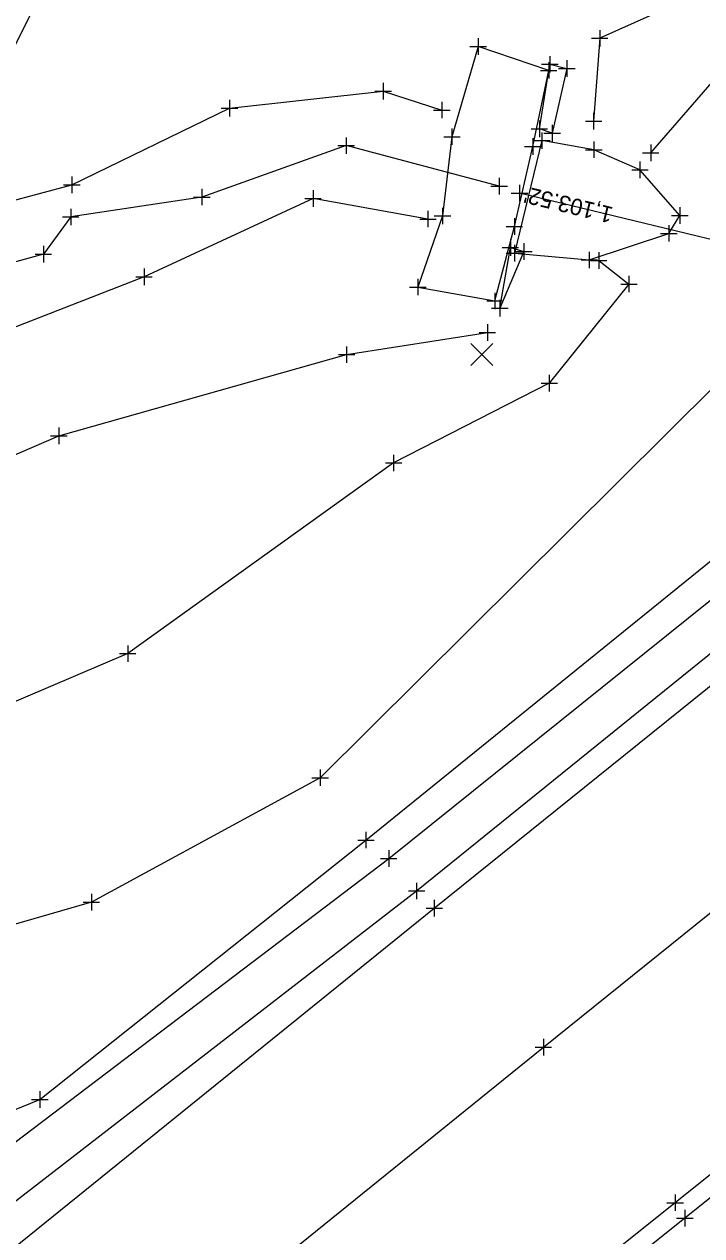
# Model space of a CAD drawing. Extents: x 2184635 to 2185378, y 369880 to 370486.
# Drawn here: x 2185068.3 to 2185109.3, y 370246.3 to 370319.8 of the extents above; entities that cross this region are included whole.
import ezdxf

# ---------------------------------------------------------------- set-up
doc = ezdxf.new("R2010")
doc.units = 0
for name, color, linetype in [('_CIVIL_CONSTRUCTION', 7, 'Continuous'), ('DR_X_Ditch', 7, 'Continuous'), ('DR_X_Headwall', 7, 'Continuous'), ('DR_X_Storm_Sewer', 7, 'Continuous'), ('GE_X_Alignment_100_Distances', 7, 'Continuous'), ('PM_X_CL_Pass_Proh_Lt', 7, 'Continuous'), ('PM_X_CL_Pass_Proh_Rt', 7, 'Continuous'), ('PM_X_Edge_Line', 7, 'Continuous'), ('PV_X_COP', 7, 'Continuous'), ('PV_X_EOP', 7, 'Continuous'), ('PV_X_Shoulder', 7, 'Continuous'), ('RD_X_Concrete_Pad', 7, 'Continuous'), ('RD_X_GR_Lt', 7, 'Continuous'), ('RW_X_CL', 7, 'Continuous'), ('RW_X_CL_100_Bearings', 7, 'Continuous'), ('SC_Scratch1', 7, 'Continuous'), ('SV_X_Break_Lines', 7, 'Continuous'), ('SV_X_Terrain_Boundary', 7, 'Continuous'), ('SV_X_Void_Area', 7, 'Continuous')]:
    doc.layers.add(name, color=color, linetype=linetype)

msp = doc.modelspace()

# ---------------------------------------------------------------- linework, layer by layer
at = {"layer": '_CIVIL_CONSTRUCTION'}
for p, q in [((2185095.352, 370299.089), (2185096.685, 370300.424)), ((2185095.352, 370300.424), (2185096.685, 370299.089))]:
    msp.add_line(p, q, dxfattribs=at)
at = {"layer": 'DR_X_Ditch'}
msp.add_lwpolyline([(2185097.066, 370309.962), (2185087.789, 370312.42), (2185079.038, 370309.308), (2185071.088, 370308.099), (2185069.431, 370305.844), (2185053.728, 370301.514), (2185050.899, 370302.622)], dxfattribs=at)
at = {"layer": 'DR_X_Headwall'}
for points in [[(2185100.132, 370317.35), (2185101.169, 370317.094), (2185100.276, 370313.173), (2185099.501, 370313.442)], [(2185097.746, 370306.249), (2185098.566, 370306.002), (2185097.102, 370302.573)]]:
    msp.add_lwpolyline(points, close=True, dxfattribs=at)
at = {"layer": 'DR_X_Storm_Sewer'}
msp.add_line((2185197.669, 370285.467), (2185098.296, 370309.544), dxfattribs=at)
at = {"layer": 'GE_X_Alignment_100_Distances'}
msp.add_lwpolyline([(2185064.938, 370249.915), (2185090.369, 370269.214), (2185130.506, 370301.429), (2185168.462, 370331.991), (2185206.748, 370363.667), (2185245.64, 370395.454)], dxfattribs=at)
at = {"layer": 'PM_X_CL_Pass_Proh_Lt'}
msp.add_lwpolyline([(2185262.142, 370374.202), (2185223.699, 370342.03), (2185185.178, 370310.659), (2185146.677, 370279.544), (2185107.738, 370248.35), (2185068.5, 370216.963), (2185029.051, 370186.04), (2184989.472, 370156.275), (2184949.89, 370125.369), (2184910.765, 370094.563), (2184870.979, 370063.529), (2184832.077, 370032.401), (2184793.204, 370001.486), (2184754.34, 369970.024), (2184715.121, 369938.505), (2184676.144, 369907.221)], dxfattribs=at)
at = {"layer": 'PM_X_CL_Pass_Proh_Rt'}
msp.add_lwpolyline([(2184772.075, 369998.33), (2184786.357, 370009.443), (2184824.962, 370040.257), (2184864.241, 370071.885), (2184905.968, 370104.805), (2184943.399, 370133.995), (2184983.483, 370165.213), (2185020.257, 370194.467), (2185061.224, 370226.635), (2185099.743, 370257.779), (2185139.182, 370289.511), (2185177.352, 370320.307), (2185216.054, 370351.804), (2185254.728, 370383.452)], dxfattribs=at)
at = {"layer": 'PM_X_Edge_Line'}
msp.add_lwpolyline([(2184661.525, 369922.948), (2184702.122, 369955.424), (2184740.459, 369986.306), (2184779.792, 370018.036), (2184818.421, 370048.832), (2184857.458, 370080.192), (2184899.139, 370112.801), (2184937.357, 370142.735), (2184976.78, 370173.64), (2185013.226, 370203.926), (2185054.743, 370235.213), (2185093.131, 370266.204), (2185132.902, 370298.208), (2185170.876, 370328.987), (2185209.713, 370360.437), (2185248.243, 370392.049)], dxfattribs=at)
at = {"layer": 'PV_X_COP'}
msp.add_lwpolyline([(2184667.936, 369914.544), (2184708.437, 369946.755), (2184746.444, 369977.522), (2184786.357, 370009.443), (2184824.962, 370040.257), (2184864.241, 370071.885), (2184905.968, 370104.805), (2184943.399, 370133.995), (2184983.483, 370165.213), (2185020.257, 370194.467), (2185061.224, 370226.635), (2185099.743, 370257.779), (2185139.182, 370289.511), (2185177.352, 370320.307), (2185216.054, 370351.804), (2185254.679, 370383.196)], dxfattribs=at)
at = {"layer": 'PV_X_EOP'}
for points in [[(2184661.562, 369922.858), (2184702.122, 369955.424), (2184740.459, 369986.306), (2184779.792, 370018.036), (2184818.421, 370048.832), (2184857.458, 370080.192), (2184899.139, 370112.801), (2184937.357, 370142.735), (2184976.78, 370173.64), (2185013.226, 370203.926), (2185054.743, 370235.213), (2185093.131, 370266.204), (2185132.902, 370298.208), (2185170.876, 370328.987), (2185209.713, 370360.437), (2185248.181, 370392.045)], [(2185262.152, 370374.256), (2185223.699, 370342.03), (2185185.178, 370310.659), (2185146.677, 370279.544), (2185107.738, 370248.35), (2185068.5, 370216.963), (2185029.051, 370186.04), (2184989.472, 370156.275), (2184949.89, 370125.369), (2184910.765, 370094.563), (2184870.979, 370063.529), (2184832.077, 370032.401), (2184793.204, 370001.486), (2184754.34, 369970.024), (2184715.121, 369938.505), (2184676.223, 369907.131)]]:
    msp.add_lwpolyline(points, dxfattribs=at)
at = {"layer": 'PV_X_Shoulder'}
for points in [[(2184660.616, 369924.653), (2184701.177, 369956.993), (2184739.308, 369987.689), (2184778.66, 370019.08), (2184817.145, 370050.202), (2184856.424, 370081.402), (2184897.962, 370114.276), (2184936.317, 370143.726), (2184975.811, 370174.815), (2184986.608, 370184.308), (2184994.082, 370192.548), (2185011.043, 370206.648), (2185033.171, 370224.287), (2185051.814, 370238.9), (2185062.885, 370246.964), (2185064.956, 370248.001), (2185067.328, 370248.113), (2185092.06, 370267.243), (2185132.002, 370299.513), (2185169.971, 370330.255), (2185208.837, 370361.607), (2185247.242, 370392.983)], [(2185263.127, 370373.08), (2185224.626, 370341.08), (2185185.979, 370309.587), (2185147.251, 370278.484), (2185108.316, 370247.412), (2185069.303, 370216.141), (2185029.865, 370185.151), (2184990.36, 370154.899), (2184951.083, 370123.826), (2184911.784, 370093.315), (2184872.077, 370062.156), (2184833.336, 370030.958), (2184794.18, 369999.967), (2184755.603, 369968.652), (2184716.02, 369937.324), (2184677.487, 369905.633)]]:
    msp.add_lwpolyline(points, dxfattribs=at)
at = {"layer": 'RD_X_Concrete_Pad'}
msp.add_lwpolyline([(2185094.202, 370312.964), (2185093.625, 370308.161), (2185092.134, 370303.852), (2185096.808, 370303.006), (2185097.986, 370307.52), (2185099.103, 370312.374), (2185100.067, 370316.984), (2185095.792, 370318.426)], close=True, dxfattribs=at)
at = {"layer": 'RD_X_GR_Lt'}
msp.add_lwpolyline([(2185046.02, 370255.484), (2185051.058, 370252.105), (2185059.685, 370250.72), (2185069.217, 370254.599), (2185088.99, 370270.332), (2185128.498, 370302.326), (2185166.722, 370333.304), (2185205.522, 370364.756), (2185244.075, 370396.55), (2185351.751, 370485.271)], dxfattribs=at)
at = {"layer": 'RW_X_CL'}
for p, q in [((2185095.792, 370318.926), (2185095.792, 370317.926)), ((2185102.66, 370318.931), (2185103.66, 370318.931)), ((2185103.16, 370319.431), (2185103.16, 370318.431)), ((2185103.16, 370318.931), (2185103.16, 370318.931)), ((2185095.292, 370318.426), (2185096.292, 370318.426)), ((2185095.792, 370318.426), (2185095.792, 370318.426)), ((2185099.632, 370317.35), (2185100.632, 370317.35)), ((2185100.067, 370317.484), (2185100.067, 370316.484)), ((2185100.132, 370317.85), (2185100.132, 370316.85)), ((2185100.132, 370317.35), (2185100.132, 370317.35)), ((2185101.169, 370317.594), (2185101.169, 370316.594)), ((2185099.567, 370316.984), (2185100.567, 370316.984)), ((2185100.067, 370316.984), (2185100.067, 370316.984)), ((2185100.669, 370317.094), (2185101.669, 370317.094)), ((2185101.169, 370317.094), (2185101.169, 370317.094)), ((2185090.033, 370316.221), (2185090.033, 370315.221)), ((2185080.719, 370315.196), (2185080.719, 370314.196)), ((2185089.533, 370315.721), (2185090.533, 370315.721)), ((2185090.033, 370315.721), (2185090.033, 370315.721)), ((2185080.219, 370314.696), (2185081.219, 370314.696)), ((2185080.719, 370314.696), (2185080.719, 370314.696)), ((2185093.093, 370314.581), (2185094.093, 370314.581)), ((2185093.593, 370315.081), (2185093.593, 370314.081)), ((2185093.593, 370314.581), (2185093.593, 370314.581)), ((2185102.793, 370314.409), (2185102.793, 370313.409)), ((2185099.501, 370313.942), (2185099.501, 370312.942)), ((2185100.276, 370313.673), (2185100.276, 370312.673)), ((2185102.293, 370313.909), (2185103.293, 370313.909)), ((2185102.793, 370313.909), (2185102.793, 370313.909)), ((2185087.789, 370312.92), (2185087.789, 370311.92)), ((2185093.702, 370312.964), (2185094.702, 370312.964)), ((2185094.202, 370313.464), (2185094.202, 370312.464)), ((2185094.202, 370312.964), (2185094.202, 370312.964)), ((2185099.001, 370313.442), (2185100.001, 370313.442)), ((2185099.501, 370313.442), (2185099.501, 370313.442)), ((2185099.651, 370313.228), (2185099.651, 370312.228)), ((2185099.776, 370313.173), (2185100.776, 370313.173)), ((2185100.276, 370313.173), (2185100.276, 370313.173)), ((2185087.289, 370312.42), (2185088.289, 370312.42)), ((2185087.789, 370312.42), (2185087.789, 370312.42)), ((2185098.603, 370312.374), (2185099.603, 370312.374)), ((2185099.103, 370312.874), (2185099.103, 370311.874)), ((2185099.103, 370312.374), (2185099.103, 370312.374)), ((2185099.151, 370312.728), (2185100.151, 370312.728)), ((2185099.651, 370312.728), (2185099.651, 370312.728)), ((2185102.802, 370312.677), (2185102.802, 370311.677)), ((2185106.25, 370312.484), (2185106.25, 370311.484)), ((2185102.302, 370312.177), (2185103.302, 370312.177)), ((2185102.802, 370312.177), (2185102.802, 370312.177)), ((2185105.597, 370311.451), (2185105.597, 370310.451)), ((2185105.75, 370311.984), (2185106.75, 370311.984)), ((2185106.25, 370311.984), (2185106.25, 370311.984)), ((2185105.097, 370310.951), (2185106.097, 370310.951)), ((2185105.597, 370310.951), (2185105.597, 370310.951)), ((2185070.662, 370310.043), (2185071.662, 370310.043)), ((2185071.162, 370310.543), (2185071.162, 370309.543)), ((2185071.162, 370310.043), (2185071.162, 370310.043)), ((2185097.066, 370310.462), (2185097.066, 370309.462)), ((2185078.538, 370309.308), (2185079.538, 370309.308)), ((2185079.038, 370309.808), (2185079.038, 370308.808)), ((2185079.038, 370309.308), (2185079.038, 370309.308)), ((2185085.782, 370309.719), (2185085.782, 370308.719)), ((2185096.566, 370309.962), (2185097.566, 370309.962)), ((2185097.066, 370309.962), (2185097.066, 370309.962)), ((2185071.088, 370308.599), (2185071.088, 370307.599)), ((2185085.282, 370309.219), (2185086.282, 370309.219)), ((2185085.782, 370309.219), (2185085.782, 370309.219)), ((2185093.625, 370308.661), (2185093.625, 370307.661)), ((2185108.016, 370308.685), (2185108.016, 370307.685)), ((2185070.588, 370308.099), (2185071.588, 370308.099)), ((2185071.088, 370308.099), (2185071.088, 370308.099)), ((2185092.248, 370307.972), (2185093.248, 370307.972)), ((2185092.748, 370308.472), (2185092.748, 370307.472)), ((2185092.748, 370307.972), (2185092.748, 370307.972)), ((2185093.125, 370308.161), (2185094.125, 370308.161)), ((2185093.625, 370308.161), (2185093.625, 370308.161)), ((2185097.986, 370308.02), (2185097.986, 370307.02)), ((2185107.516, 370308.185), (2185108.516, 370308.185)), ((2185108.016, 370308.185), (2185108.016, 370308.185)), ((2185097.486, 370307.52), (2185098.486, 370307.52)), ((2185097.986, 370307.52), (2185097.986, 370307.52)), ((2185106.846, 370307.101), (2185107.846, 370307.101)), ((2185107.346, 370307.601), (2185107.346, 370306.601)), ((2185107.346, 370307.101), (2185107.346, 370307.101)), ((2185069.431, 370306.344), (2185069.431, 370305.344)), ((2185097.746, 370306.749), (2185097.746, 370305.749)), ((2185097.992, 370306.404), (2185097.992, 370305.404)), ((2185098.566, 370306.502), (2185098.566, 370305.502)), ((2185068.931, 370305.844), (2185069.931, 370305.844)), ((2185069.431, 370305.844), (2185069.431, 370305.844)), ((2185097.246, 370306.249), (2185098.246, 370306.249)), ((2185097.492, 370305.904), (2185098.492, 370305.904)), ((2185097.746, 370306.249), (2185097.746, 370306.249)), ((2185097.992, 370305.904), (2185097.992, 370305.904)), ((2185098.066, 370306.002), (2185099.066, 370306.002)), ((2185098.566, 370306.002), (2185098.566, 370306.002)), ((2185102.527, 370305.99), (2185102.527, 370304.99)), ((2185103.101, 370305.956), (2185103.101, 370304.956)), ((2185075.536, 370304.974), (2185075.536, 370303.974)), ((2185102.027, 370305.49), (2185103.027, 370305.49)), ((2185102.527, 370305.49), (2185102.527, 370305.49)), ((2185102.601, 370305.456), (2185103.601, 370305.456)), ((2185103.101, 370305.456), (2185103.101, 370305.456)), ((2185075.036, 370304.474), (2185076.036, 370304.474)), ((2185075.536, 370304.474), (2185075.536, 370304.474)), ((2185092.134, 370304.352), (2185092.134, 370303.352)), ((2185104.93, 370304.533), (2185104.93, 370303.533)), ((2185091.634, 370303.852), (2185092.634, 370303.852)), ((2185092.134, 370303.852), (2185092.134, 370303.852)), ((2185096.808, 370303.506), (2185096.808, 370302.506)), ((2185104.43, 370304.033), (2185105.43, 370304.033)), ((2185104.93, 370304.033), (2185104.93, 370304.033)), ((2185096.308, 370303.006), (2185097.308, 370303.006)), ((2185096.808, 370303.006), (2185096.808, 370303.006)), ((2185097.102, 370303.073), (2185097.102, 370302.073)), ((2185096.602, 370302.573), (2185097.602, 370302.573)), ((2185097.102, 370302.573), (2185097.102, 370302.573)), ((2185096.348, 370301.593), (2185096.348, 370300.593)), ((2185095.848, 370301.093), (2185096.848, 370301.093)), ((2185096.348, 370301.093), (2185096.348, 370301.093)), ((2185087.315, 370299.755), (2185088.315, 370299.755)), ((2185087.815, 370300.255), (2185087.815, 370299.255)), ((2185087.815, 370299.755), (2185087.815, 370299.755)), ((2185100.103, 370298.521), (2185100.103, 370297.521)), ((2185099.603, 370298.021), (2185100.603, 370298.021)), ((2185100.103, 370298.021), (2185100.103, 370298.021)), ((2185070.374, 370295.331), (2185070.374, 370294.331)), ((2185069.874, 370294.831), (2185070.874, 370294.831)), ((2185070.374, 370294.831), (2185070.374, 370294.831)), ((2185090.168, 370293.19), (2185091.168, 370293.19)), ((2185090.668, 370293.69), (2185090.668, 370292.69)), ((2185090.668, 370293.19), (2185090.668, 370293.19)), ((2185074.547, 370282.128), (2185074.547, 370281.128)), ((2185074.047, 370281.628), (2185075.047, 370281.628)), ((2185074.547, 370281.628), (2185074.547, 370281.628)), ((2185085.714, 370274.11), (2185086.714, 370274.11)), ((2185086.214, 370274.61), (2185086.214, 370273.61)), ((2185086.214, 370274.11), (2185086.214, 370274.11)), ((2185088.49, 370270.332), (2185089.49, 370270.332)), ((2185088.99, 370270.832), (2185088.99, 370269.832)), ((2185088.99, 370270.332), (2185088.99, 370270.332)), ((2185090.369, 370269.714), (2185090.369, 370268.714)), ((2185089.869, 370269.214), (2185090.869, 370269.214)), ((2185090.369, 370269.214), (2185090.369, 370269.214)), ((2185092.06, 370267.743), (2185092.06, 370266.743)), ((2185072.344, 370267.061), (2185072.344, 370266.061)), ((2185091.56, 370267.243), (2185092.56, 370267.243)), ((2185092.06, 370267.243), (2185092.06, 370267.243)), ((2185093.131, 370266.704), (2185093.131, 370265.704)), ((2185093.131, 370266.704), (2185093.131, 370265.704)), ((2185071.844, 370266.561), (2185072.844, 370266.561)), ((2185072.344, 370266.561), (2185072.344, 370266.561)), ((2185092.631, 370266.204), (2185093.631, 370266.204)), ((2185092.631, 370266.204), (2185093.631, 370266.204)), ((2185093.131, 370266.204), (2185093.131, 370266.204)), ((2185093.131, 370266.204), (2185093.131, 370266.204)), ((2185099.743, 370258.279), (2185099.743, 370257.279)), ((2185099.743, 370258.279), (2185099.743, 370257.279)), ((2185099.243, 370257.779), (2185100.243, 370257.779)), ((2185099.243, 370257.779), (2185100.243, 370257.779)), ((2185099.743, 370257.779), (2185099.743, 370257.779)), ((2185099.743, 370257.779), (2185099.743, 370257.779)), ((2185069.217, 370255.099), (2185069.217, 370254.099)), ((2185068.717, 370254.599), (2185069.717, 370254.599)), ((2185069.217, 370254.599), (2185069.217, 370254.599)), ((2185107.238, 370248.35), (2185108.238, 370248.35)), ((2185107.238, 370248.35), (2185108.238, 370248.35)), ((2185107.738, 370248.85), (2185107.738, 370247.85)), ((2185107.738, 370248.85), (2185107.738, 370247.85)), ((2185107.738, 370248.35), (2185107.738, 370248.35)), ((2185107.738, 370248.35), (2185107.738, 370248.35)), ((2185108.316, 370247.912), (2185108.316, 370246.912)), ((2185107.816, 370247.412), (2185108.816, 370247.412)), ((2185108.316, 370247.412), (2185108.316, 370247.412))]:
    msp.add_line(p, q, dxfattribs=at)
at = {"layer": 'RW_X_CL_100_Bearings'}
for p, q in [((2185098.296, 370310.044), (2185098.296, 370309.044)), ((2185097.796, 370309.544), (2185098.796, 370309.544)), ((2185098.296, 370309.544), (2185098.296, 370309.544))]:
    msp.add_line(p, q, dxfattribs=at)
at = {"layer": 'SV_X_Break_Lines'}
for points in [[(2185238.668, 370405.318), (2185202.581, 370371.499), (2185173.504, 370347.593), (2185162.544, 370339.328), (2185125.289, 370312.922), (2185086.214, 370274.11), (2185072.344, 370266.561), (2185063.517, 370264.024), (2185054.122, 370264.296), (2185046.494, 370262.377), (2185041.8, 370263.72), (2185037.874, 370271.942)], [(2185106.25, 370311.984), (2185110.377, 370316.731), (2185120.337, 370325.775), (2185107.52, 370320.878), (2185103.16, 370318.931), (2185102.793, 370313.909)], [(2185059.374, 370306.895), (2185071.162, 370310.043), (2185080.719, 370314.696), (2185090.033, 370315.721), (2185093.593, 370314.581)], [(2185092.748, 370307.972), (2185085.782, 370309.219), (2185075.536, 370304.474), (2185061.386, 370298.945), (2185053.561, 370294.222), (2185046.7, 370291.65)], [(2185103.101, 370305.456), (2185104.93, 370304.033), (2185100.103, 370298.021), (2185090.668, 370293.19), (2185074.547, 370281.628), (2185060.325, 370275.571), (2185051.642, 370270.982), (2185047.413, 370267.993)], [(2185049.198, 370271.897), (2185048.788, 370280.746), (2185048.621, 370285.205), (2185058.85, 370289.868), (2185070.374, 370294.831), (2185087.815, 370299.755), (2185096.348, 370301.093)]]:
    msp.add_lwpolyline(points, dxfattribs=at)
at = {"layer": 'SV_X_Terrain_Boundary'}
msp.add_lwpolyline([(2184974.137, 370097.077), (2185033.603, 370139.079), (2185056.498, 370157.156), (2185084.693, 370178.208), (2185162.576, 370240.184), (2185199.27, 370262.443), (2185215.204, 370306.943), (2185268.576, 370364.897), (2185258.835, 370377.241), (2185248.181, 370392.045), (2185238.668, 370405.318), (2185197.578, 370376.275), (2185164.413, 370344.459), (2185149.44, 370353.437), (2185069.982, 370323.057), (2185048.788, 370280.746), (2184981.838, 370244.628)], dxfattribs=at)
at = {"layer": 'SV_X_Void_Area'}
msp.add_lwpolyline([(2185097.992, 370305.904), (2185102.527, 370305.49), (2185107.346, 370307.101), (2185108.016, 370308.185), (2185105.597, 370310.951), (2185102.802, 370312.177), (2185099.651, 370312.728)], close=True, dxfattribs=at)

# ---------------------------------------------------------------- texts
at = {"layer": 'SC_Scratch1'}
msp.add_text("1,103.52'", height=1, rotation=166.38022, dxfattribs=at).set_placement((2185104.032, 370308.669))

doc.saveas('drawing.dxf')
